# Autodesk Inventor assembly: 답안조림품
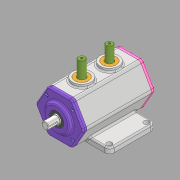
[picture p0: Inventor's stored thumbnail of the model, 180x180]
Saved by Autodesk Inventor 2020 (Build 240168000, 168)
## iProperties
Created: 2021-06
Part Number: 답안조림품
Document SubType Name: Assembly
Designer: MIRAE
Author: MIRAE
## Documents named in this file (11)
- C:\Users\MIRAE\Desktop\710606v1030\답안조림품.iam
- C:\Users\MIRAE\Desktop\710606v1030\본체.ipt
- C:\Users\MIRAE\Desktop\710606v1030\뒷커버.ipt
- C:\Users\MIRAE\Desktop\710606v1030\베어링 6203.ipt
- C:\Users\MIRAE\Desktop\710606v1030\베어링 6302.ipt
- C:\Users\MIRAE\Desktop\710606v1030\볼트 M4.ipt
- C:\Users\MIRAE\Desktop\710606v1030\부시.ipt
- C:\Users\MIRAE\Desktop\710606v1030\슬라이더.ipt
- C:\Users\MIRAE\Desktop\710606v1030\앞커버.ipt
- C:\Users\MIRAE\Desktop\710606v1030\오일실.ipt
- C:\Users\MIRAE\Desktop\710606v1030\편심축.ipt
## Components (10 placed, 3 different names)
1. 7-베어링 6203:1
2. 8-오일실:1
3. 9-M4-소켓머리:1 — 각도:1
4. 9-M4-소켓머리:3
5. 9-M4-소켓머리:4
6. 9-M4-소켓머리:5
7. 9-M4-소켓머리:2 — 각도:2
8. 9-M4-소켓머리:6
9. 9-M4-소켓머리:7
10. 9-M4-소켓머리:8
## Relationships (2: Angle 2)
- 각도:1 [Angle]: 9-M4-소켓머리:1
- 각도:2 [Angle]: 9-M4-소켓머리:2
